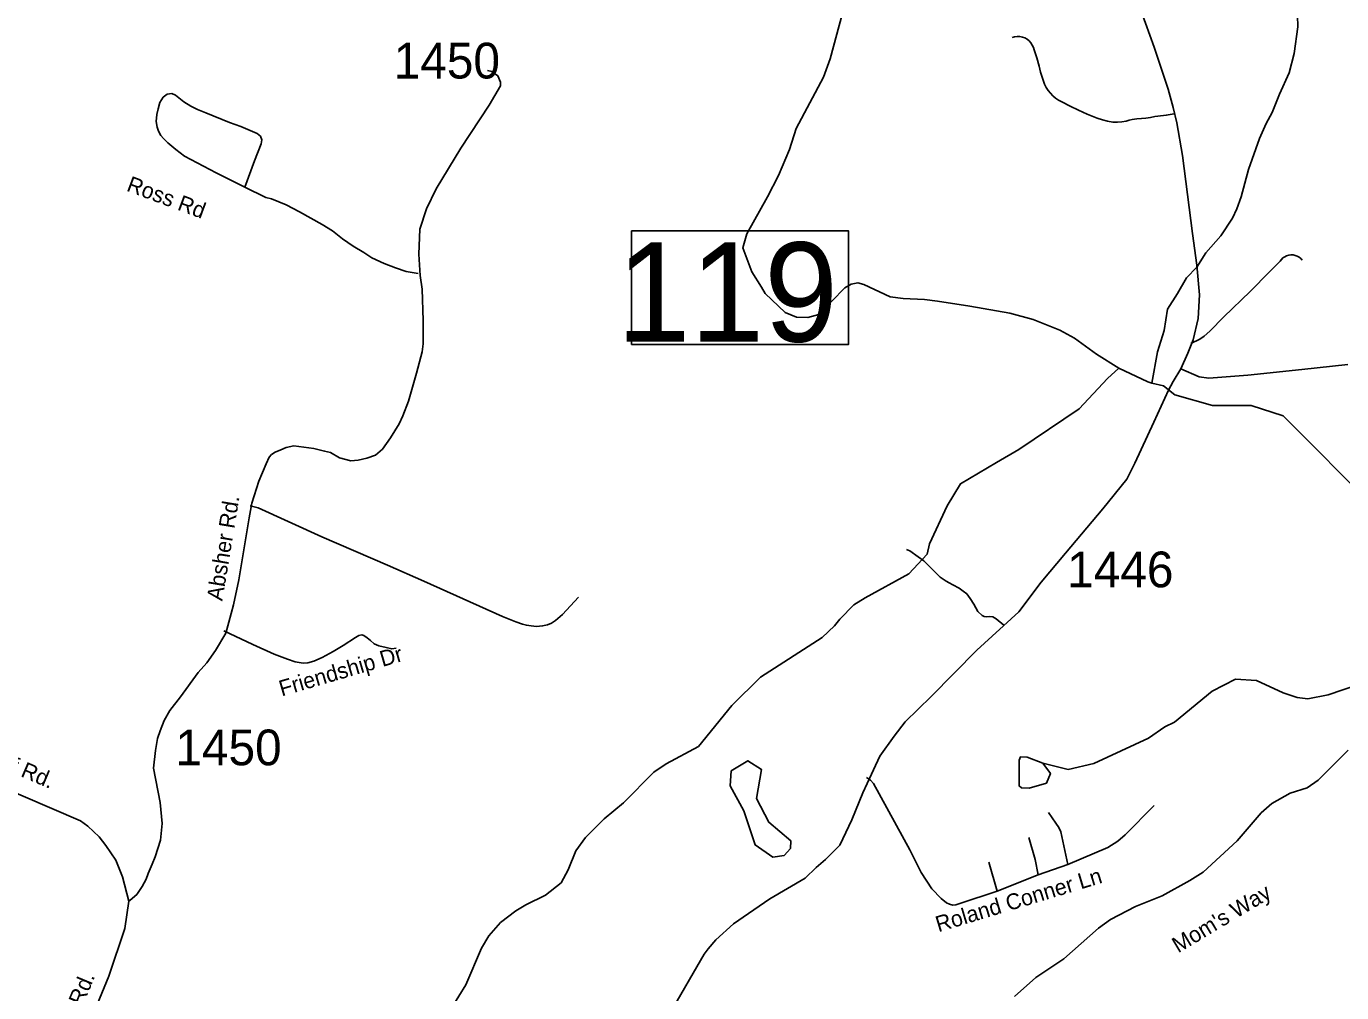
# Model space of a CAD drawing. Extents: x 1268485 to 1426702, y 514839 to 616766.
# Drawn here: x 1317709 to 1323145, y 575334 to 579327 of the extents above; entities that cross this region are included whole.
import ezdxf

# ---------------------------------------------------------------- set-up
doc = ezdxf.new("R2010")
doc.units = 0
for name, color, linetype in [('Old_Level_10', 7, 'Continuous'), ('Old_Level_11', 7, 'Continuous'), ('Old_Level_31', 7, 'Continuous'), ('Old_Level_32', 7, 'Continuous'), ('Old_Level_35', 7, 'Continuous'), ('Old_Level_50', 7, 'Continuous'), ('Old_Level_59', 7, 'Continuous'), ('Old_Level_62', 7, 'Continuous'), ('Old_Level_8', 7, 'Continuous')]:
    doc.layers.add(name, color=color, linetype=linetype)

msp = doc.modelspace()

# ---------------------------------------------------------------- linework, layer by layer
at = {"layer": 'Old_Level_31'}
msp.add_line((1322429.85, 577824.303), (1322429.85, 577824.303), dxfattribs=at)
msp.add_lwpolyline([(1320210.266, 578481.649), (1321106.769, 578481.649), (1321106.769, 578012.522), (1320210.266, 578012.522), (1320210.266, 578481.649)], dxfattribs=at)
at = {"layer": 'Old_Level_32'}
for points in [[(1322480.057, 577911.656), (1322508.528, 577976.994), (1322530.303, 578030.975), (1322551.456, 578119.649), (1322557.213, 578217.134), (1322545.848, 578339.946), (1322527.761, 578471.506), (1322486.53, 578792.879), (1322463.567, 578927.662), (1322448.259, 578991.991), (1322427.822, 579067.263), (1322370.126, 579241.192), (1322298.24, 579440.453)], [(1318133.384, 575712.187), (1318138.454, 575716.415), (1318165.501, 575740.094), (1318187.475, 575773.076), (1318204.379, 575803.522), (1318212.83, 575827.201), (1318229.734, 575865.257), (1318241.567, 575894.857), (1318263.541, 575964.204), (1318270.303, 576033.551), (1318261.851, 576119.812), (1318235.279, 576261.621), (1318243.257, 576334.618), (1318251.709, 576383.669), (1318261.851, 576415.806), (1318278.754, 576458.09), (1318302.42, 576500.375), (1318346.551, 576556.985), (1318419.054, 576656.998), (1318454.552, 576697.591), (1318491.066, 576747.773), (1318533.787, 576819.166), (1318546.528, 576864.468), (1318565.497, 576936.168), (1318587.795, 577039.771), (1318630.228, 577296.756), (1318641.203, 577356.653), (1318670.029, 577447.477), (1318700.646, 577519.468), (1318712.892, 577547.038), (1318722.077, 577557.761), (1318737.385, 577566.951), (1318760.347, 577577.672), (1318782.578, 577586.88), (1318814.725, 577593.006), (1318897.389, 577582.285), (1318941.783, 577571.564), (1318966.276, 577565.437), (1319003.015, 577543.994), (1319050.471, 577531.741), (1319081.087, 577534.804), (1319116.296, 577542.463), (1319151.504, 577554.716), (1319180.59, 577579.222), (1319214.386, 577626.687), (1319249.476, 577684.904), (1319264.785, 577717.068), (1319287.865, 577778.327), (1319321.542, 577893.207), (1319344.505, 577981.739), (1319349.097, 578014.825), (1319349.097, 578111.629), (1319344.387, 578240.887), (1319336.733, 578297.558), (1319330.61, 578385.779), (1319335.202, 578488.399), (1319362.757, 578572.639), (1319402.558, 578655.347), (1319505.123, 578824.132), (1319622.25, 579000.941), (1319668.92, 579081.446), (1319668.92, 579096.762), (1319658.205, 579122.8), (1319632.182, 579139.648), (1319615.342, 579144.243)], [(1322429.562, 577824.042), (1322448.118, 577858.857), (1322480.057, 577911.656)], [(1322480.057, 577911.656), (1322556.36, 577878.198), (1322595.79, 577873.557), (1322756.607, 577885.162), (1322980.005, 577909.649), (1323169.633, 577929.728)], [(1320226.05, 575003.326), (1320510.031, 575492.645), (1320526.935, 575514.632), (1320559.051, 575551.843), (1320631.579, 575618.457), (1320694.123, 575660.741), (1320782.178, 575721.489), (1320927.55, 575807.75), (1320973.189, 575851.726), (1321012.068, 575883.863), (1321071.073, 575943.88), (1321120.094, 576048.746), (1321165.733, 576159.193), (1321184.327, 576198.096), (1321236.728, 576311.418), (1321295.891, 576394.296), (1321341.531, 576453.495), (1321448.024, 576558.361), (1321636.93, 576748.763), (1321809.912, 576908.052), (1321902.368, 577030.759), (1322003.839, 577149.603), (1322157.337, 577333.147), (1322256.492, 577455.992), (1322289.543, 577522.139), (1322367.709, 577691.744), (1322429.562, 577824.042)], [(1317575.901, 576197.334), (1317933.018, 576044.382), (1317963.778, 576021.619), (1318010.732, 575978.453), (1318038.009, 575941.887), (1318079.292, 575882.171), (1318106.337, 575812.824), (1318133.384, 575712.187)], [(1318133.384, 575712.187), (1318116.48, 575599.709), (1318050.556, 575401.816), (1317960.17, 575185.167)]]:
    msp.add_lwpolyline(points, dxfattribs=at)
at = {"layer": 'Old_Level_35'}
for p, q in [((1321721.336, 575754.057), (1321686.375, 575873.244)), ((1321890.606, 575821.366), (1322012.92, 575864.375)), ((1321721.336, 575754.057), (1321890.606, 575821.366))]:
    msp.add_line(p, q, dxfattribs=at)
for points in [[(1322452.142, 578965.122), (1322419.538, 578959.483), (1322385.5, 578955.587), (1322372.786, 578953.947), (1322354.332, 578950.102), (1322335.774, 578947.385), (1322317.115, 578945.54), (1322297.635, 578944.514), (1322278.257, 578941.694), (1322265.954, 578938.875), (1322254.266, 578935.543), (1322236.119, 578932.262), (1322217.767, 578930.571), (1322199.21, 578930.571), (1322177.269, 578934.877), (1322155.636, 578940.516), (1322134.208, 578947.333), (1322113.395, 578955.33), (1322092.993, 578964.507), (1322057.211, 578979.937), (1322022.25, 578996.803), (1321987.904, 579015.052), (1321974.883, 579022.229), (1321962.58, 579030.585), (1321951.199, 579040.069), (1321940.742, 579050.577), (1321931.412, 579062.06), (1321923.107, 579074.363), (1321916.135, 579087.384), (1321907.728, 579112.042), (1321900.756, 579137.109), (1321895.015, 579162.485), (1321884.455, 579196.011), (1321873.279, 579229.229), (1321870.614, 579239.738), (1321866.205, 579249.632), (1321860.361, 579258.757), (1321853.082, 579266.805), (1321844.777, 579273.623), (1321835.242, 579279.005), (1321825.092, 579282.748), (1321814.532, 579284.901), (1321803.767, 579285.311), (1321793.002, 579283.978), (1321782.646, 579281.005)], [(1318612.029, 578662.67), (1318652.116, 578771.604), (1318679.491, 578841.066), (1318682.361, 578857.213), (1318676.723, 578872.387), (1318663.087, 578883.511), (1318595.419, 578912.526), (1318549.078, 578928.828), (1318451.575, 578969.069), (1318417.229, 578983.884), (1318388.419, 578997.264), (1318360.532, 579014.693), (1318325.263, 579043.042), (1318309.987, 579049.244), (1318291.327, 579046.989), (1318274.923, 579033.917)], [(1318612.029, 578662.67), (1318493.098, 578722.084), (1318362.583, 578790.11), (1318327.006, 578817.69), (1318294.095, 578845.679), (1318275.641, 578862.749), (1318265.388, 578875.668), (1318255.341, 578893.764), (1318250.214, 578910.322), (1318246.113, 578933.954), (1318248.164, 578961.944), (1318254.623, 578986.088), (1318261.492, 579012.437), (1318274.923, 579033.917)], [(1319328.276, 578305.213), (1319278.961, 578314.184), (1319235.079, 578328.333), (1319188.328, 578346.89), (1319137.167, 578370.266), (1319104.051, 578391.694), (1319060.17, 578418.504), (1319015.776, 578448.749), (1318974.151, 578482.122), (1318931.705, 578508.164), (1318838.406, 578559.888), (1318782.529, 578589.825), (1318722.347, 578613.919), (1318698.458, 578619.814), (1318612.029, 578662.67)], [(1322520.834, 578016.039), (1322558.769, 578034.442), (1322576.301, 578046.694), (1322599.676, 578067.455), (1322657.604, 578127.125), (1322766.589, 578231.804), (1322846.252, 578313.107), (1322890.338, 578356.373), (1322895.669, 578363.55), (1322901.923, 578369.804), (1322909.203, 578374.931), (1322917.2, 578378.878), (1322925.709, 578381.441), (1322934.629, 578382.569), (1322943.549, 578382.262), (1322952.264, 578380.569), (1322960.671, 578377.443), (1322968.36, 578372.983), (1322975.229, 578367.395), (1322981.176, 578360.679)], [(1318634.892, 577346.184), (1318667.085, 577337.624), (1318930.167, 577217.924), (1319201.041, 577100.019), (1319351.754, 577034.197), (1319677.582, 576889.021), (1319732.126, 576866.311), (1319759.09, 576857.289), (1319775.904, 576852.419), (1319795.897, 576849.548), (1319817.222, 576847.395), (1319842.649, 576849.292), (1319862.846, 576854.213), (1319879.25, 576861.493), (1319895.962, 576871.95), (1319924.259, 576896.915), (1319991.414, 576968.683)], [(1321748.403, 576851.958), (1321717.337, 576878.512), (1321703.291, 576887.38), (1321688.117, 576888.252), (1321675.302, 576887.227), (1321666.895, 576888.713), (1321659.205, 576892.506), (1321641.673, 576909.526), (1321624.346, 576939.618), (1321609.89, 576962.481), (1321595.126, 576981.961), (1321579.85, 576993.495), (1321564.163, 577005.695), (1321538.327, 577019.383), (1321522.845, 577027.79), (1321510.542, 577034.864), (1321498.547, 577042.451), (1321486.141, 577051.319), (1321472.403, 577063.264), (1321417.859, 577119.038), (1321394.483, 577135.493), (1321360.342, 577159.639), (1321345.783, 577165.123)], [(1318524.779, 576829.3), (1318645.145, 576772.756), (1318734.035, 576733.335), (1318788.989, 576711.548), (1318820.156, 576700.885), (1318852.965, 576695.759)], [(1318852.965, 576695.759), (1318872.957, 576696.477), (1318897.974, 576704.064), (1318931.295, 576718.982), (1318977.636, 576743.383), (1319018.544, 576768.86), (1319068.987, 576801.771), (1319083.648, 576809.665), (1319095.029, 576812.383)], [(1319095.029, 576812.383), (1319104.154, 576809.665), (1319118.2, 576800.08), (1319131.22, 576788.699), (1319146.599, 576775.114), (1319165.874, 576767.169), (1319195.914, 576759.838), (1319219.085, 576754.148), (1319237.232, 576758.044)], [(1321181.741, 576223.268), (1321197.325, 576211.734), (1321209.526, 576198.047), (1321360.752, 575924.2), (1321407.299, 575830.696), (1321450.77, 575762.875), (1321489.217, 575723.505), (1321512.285, 575705.307), (1321523.358, 575700.026), (1321537.404, 575695.977), (1321550.835, 575697.31), (1321566.727, 575702.641), (1321721.336, 575754.057)], [(1322012.92, 575864.375), (1322177.782, 575934.298), (1322220.228, 575959.622), (1322249.755, 575986.894), (1322369.3, 576107.977)], [(1322012.92, 575864.375), (1321984.623, 575999.044), (1321975.293, 576016.319), (1321963.4, 576034.518), (1321933.667, 576078.809)], [(1321890.606, 575821.366), (1321877.791, 575884.317), (1321851.544, 575975.77)]]:
    msp.add_lwpolyline(points, dxfattribs=at)
at = {"layer": 'Old_Level_50'}
msp.add_line((1322429.85, 577824.303), (1322429.85, 577824.303), dxfattribs=at)
at = {"layer": 'Old_Level_59'}
for points in [[(1321081.471, 579380.968), (1321031.028, 579192.063), (1321003.346, 579116.656), (1320890.26, 578905.144), (1320862.27, 578817.74), (1320817.671, 578710.755), (1320771.637, 578621.762), (1320686.028, 578469.665), (1320670.649, 578411.994), (1320707.71, 578312.13), (1320746.726, 578249.669), (1320762.333, 578222.342), (1320844.533, 578143.786), (1320892.208, 578124.664), (1320938.139, 578123.639), (1320984.481, 578136.557), (1321091.108, 578246.107), (1321117.458, 578261.486), (1321145.55, 578266.868), (1321169.438, 578260.306), (1321278.321, 578209.761), (1321332.147, 578202.533), (1321420.217, 578198.432), (1321474.043, 578191.204), (1321607.532, 578170.083), (1321773.112, 578142.196), (1321870.409, 578115.95), (1321979.496, 578071.351), (1322040.807, 578037.979), (1322131.338, 577971.798), (1322223.902, 577914.562)], [(1322223.902, 577914.562), (1322343.948, 577857.723), (1322360.11, 577853.091)], [(1323284.755, 577335.325), (1322902.988, 577717.825), (1322770.012, 577759.86), (1322611.254, 577759.827), (1322455.849, 577804.7), (1322408.687, 577841.063), (1322360.11, 577853.091)]]:
    msp.add_lwpolyline(points, dxfattribs=at)
at = {"layer": 'Old_Level_62'}
for points in [[(1322959.921, 579598.85), (1322958.793, 579466.797), (1322963.509, 579324.593), (1322948.848, 579214.942), (1322927.01, 579135.33), (1322887.025, 579046.235), (1322857.087, 578970.93), (1322832.174, 578925.459), (1322804.594, 578864.046), (1322759.585, 578735.018), (1322729.032, 578621.726), (1322711.705, 578572.104), (1322692.841, 578534.477), (1322645.269, 578461.529), (1322583.548, 578390.94), (1322546.126, 578331.783), (1322503.338, 578287.643), (1322466.375, 578222.923), (1322424.793, 578158.202), (1322410.933, 578070.367), (1322383.211, 577982.532), (1322360.11, 577853.091)], [(1319466.891, 575272.237), (1319525.228, 575366.971), (1319590.845, 575517.53), (1319619.962, 575568.844), (1319669.277, 575623.747), (1319732.433, 575672.293), (1319773.034, 575697.36), (1319854.029, 575737.5), (1319919.133, 575787.993), (1319948.456, 575841.359), (1319980.341, 575920.662), (1320019.711, 575975.77), (1320097.426, 576052.05), (1320177.089, 576118.179), (1320302.068, 576245.414), (1320352.921, 576280.221), (1320486.717, 576351.169), (1320624.717, 576520.029), (1320743.443, 576637.371), (1320997.4, 576801.463), (1321048.56, 576850.368), (1321071.218, 576877.845), (1321128.53, 576936.542), (1321175.282, 576965.403), (1321355.728, 577065.315), (1321431.893, 577146.463), (1321441.134, 577188.069), (1321515.058, 577345.248), (1321570.046, 577437.03), (1321717.893, 577524.866), (1321810.764, 577578.805), (1322060.467, 577746.671), (1322177.516, 577871.594), (1322223.902, 577914.562)], [(1321910.187, 576282.259), (1322014.227, 576256.328), (1322119.957, 576281.144), (1322346.437, 576385.874), (1322413.592, 576432.37), (1322454.09, 576451.439), (1322609.109, 576579.905), (1322706.304, 576629.681), (1322792.22, 576623.735), (1322903.051, 576573.087), (1322960.671, 576553.71), (1323004.552, 576548.737), (1323089.136, 576564.731), (1323214.115, 576607.843), (1323286.498, 576620.197), (1323356.011, 576600.564), (1323421.218, 576567.038), (1323462.228, 576520.029)], [(1321793.309, 575318.168), (1321881.174, 575396.191), (1321997.131, 575473.546), (1322140.052, 575600.32), (1322188.957, 575637.127), (1322292.201, 575690.799), (1322403.339, 575734.27), (1322516.835, 575797.631), (1322571.687, 575832.387), (1322712.865, 575961.16), (1322811.598, 576076.964), (1322856.504, 576115.923), (1322931.451, 576158.215), (1323002.091, 576180.515), (1323046.895, 576211.529), (1323171.874, 576336.662)], [(1320622.268, 576251.131), (1320690.308, 576292.706), (1320746.921, 576256.328), (1320726.146, 576136.801), (1320778.085, 576038.061), (1320867.807, 575962.083), (1320867.089, 575930.095), (1320840.33, 575900.67), (1320794.193, 575893.698), (1320720.952, 575944.518), (1320674.207, 576084.833), (1320617.075, 576188.769), (1320622.268, 576251.131)], [(1321910.187, 576282.259), (1321941.15, 576239.558), (1321924.336, 576199.931), (1321853.798, 576179.528), (1321821.81, 576180.348), (1321811.865, 576188.55), (1321812.377, 576294.614), (1321816.786, 576308.506), (1321844.776, 576307.84), (1321910.187, 576282.259)]]:
    msp.add_lwpolyline(points, dxfattribs=at)

# ---------------------------------------------------------------- texts
at = {"layer": 'Old_Level_10'}
for s, height, rotation, p in [('Ross Rd', 65.6167, 339.5634, (1318119.534, 578648.397)), ('Friendship Dr', 65.61666, 16.308967, (1318764.521, 576557.829)), ('Roland Conner Ln', 65.61666, 16.761872, (1321478.013, 575583.667)), ("Mom's Way", 65.6167, 30.898442, (1322468.801, 575496.245))]:
    msp.add_text(s, height=height, rotation=rotation, dxfattribs=at).set_placement(p)
at = {"layer": 'Old_Level_11'}
for s, height, rotation, p in [('Absher Rd.', 65.6167, 80.623906, (1318519.099, 576950.363)), ('Biggerstaff Rd.', 65.61666, 336.982206, (1317273.781, 576402.614)), ('Dameron  Rd.', 65.61666, 67.354142, (1317784.218, 574898.849))]:
    msp.add_text(s, height=height, rotation=rotation, dxfattribs=at).set_placement(p)
at = {"layer": 'Old_Level_31'}
msp.add_text('119', height=410.1042, dxfattribs=at).set_placement((1320148.311, 578024.036))
at = {"layer": 'Old_Level_8'}
for s, p in [('1450', (1319227.311, 579111.263)), ('1446', (1322010.366, 577009.056)), ('1450', (1318325.112, 576273.741))]:
    msp.add_text(s, height=147.6375, dxfattribs=at).set_placement(p)

doc.saveas('drawing.dxf')
